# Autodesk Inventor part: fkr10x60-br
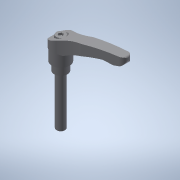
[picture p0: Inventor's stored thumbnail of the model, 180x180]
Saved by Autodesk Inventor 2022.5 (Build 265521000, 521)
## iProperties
Created: 2017-09
Part Number: fkr10x60-br
Material: 一般
Document SubType Name: Modeling
Designer: imaocorp
Density: 1 g/cm^3
Appearance: 既定
Author: imaocorp
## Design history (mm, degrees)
node "fkr10x60-br.x_t1"
node "fkr10x60-br"
node "Base1"
